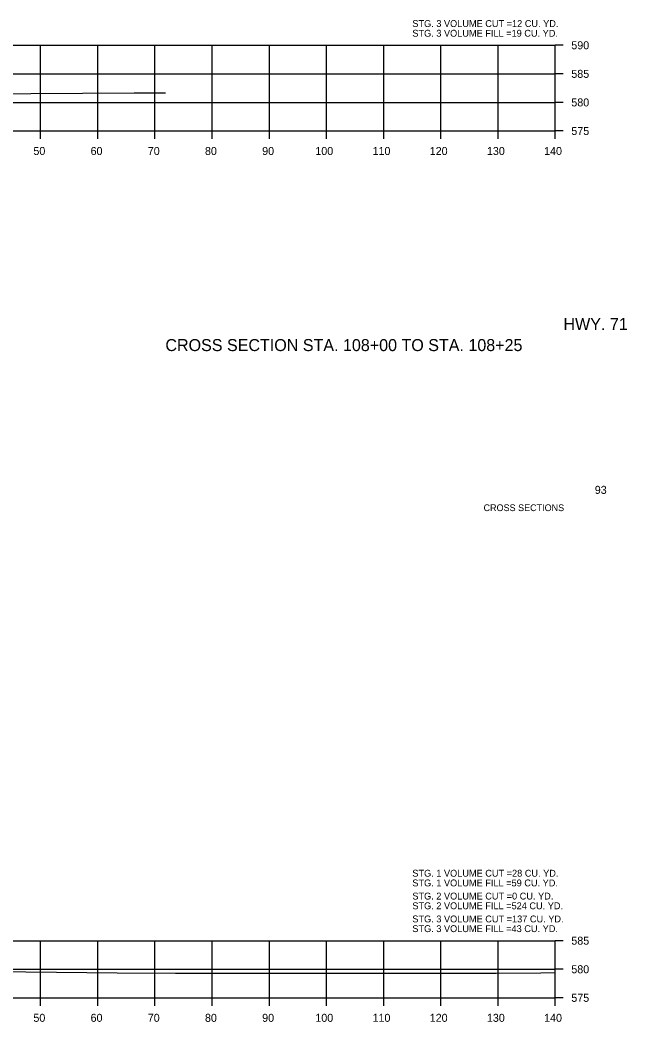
# Model space of a CAD drawing. Extents: x 642114 to 642416, y 286928 to 293347.
# Drawn here: x 642306.6 to 642412.8, y 288365.5 to 288540.8 of the extents above; entities that cross this region are included whole.
import ezdxf

# ---------------------------------------------------------------- set-up
doc = ezdxf.new("R2010")
doc.units = 0
for name, color, linetype in [('R_Axis', 7, 'Continuous'), ('R_Axis Annot', 7, 'Continuous'), ('R_Border', 7, 'Continuous'), ('R_Border Notes', 7, 'Continuous'), ('R_Draft', 7, 'Continuous'), ('R_Exist Surface Annot', 7, 'Continuous'), ('R_Grid', 7, 'Continuous')]:
    doc.layers.add(name, color=color, linetype=linetype)

msp = doc.modelspace()

# ---------------------------------------------------------------- linework, layer by layer
at = {"layer": 'R_Axis'}
for p, q in [((642400.24, 288521.41), (642400.24, 288536.41)), ((642401.64, 288536.41), (642400.24, 288536.41)), ((642401.64, 288531.41), (642400.24, 288531.41)), ((642401.64, 288526.41), (642400.24, 288526.41)), ((642120.24, 288521.41), (642400.24, 288521.41)), ((642310.24, 288520.01), (642310.24, 288521.41)), ((642320.24, 288520.01), (642320.24, 288521.41)), ((642330.24, 288520.01), (642330.24, 288521.41)), ((642340.24, 288520.01), (642340.24, 288521.41)), ((642350.24, 288520.01), (642350.24, 288521.41)), ((642360.24, 288520.01), (642360.24, 288521.41)), ((642370.24, 288520.01), (642370.24, 288521.41)), ((642380.24, 288520.01), (642380.24, 288521.41)), ((642390.24, 288520.01), (642390.24, 288521.41)), ((642400.24, 288520.01), (642400.24, 288521.41)), ((642401.64, 288521.41), (642400.24, 288521.41)), ((642400.24, 288369.74), (642400.24, 288379.74)), ((642401.64, 288379.74), (642400.24, 288379.74)), ((642401.64, 288374.74), (642400.24, 288374.74)), ((642120.24, 288369.74), (642400.24, 288369.74)), ((642310.24, 288368.34), (642310.24, 288369.74)), ((642320.24, 288368.34), (642320.24, 288369.74)), ((642330.24, 288368.34), (642330.24, 288369.74)), ((642340.24, 288368.34), (642340.24, 288369.74)), ((642350.24, 288368.34), (642350.24, 288369.74)), ((642360.24, 288368.34), (642360.24, 288369.74)), ((642370.24, 288368.34), (642370.24, 288369.74)), ((642380.24, 288368.34), (642380.24, 288369.74)), ((642390.24, 288368.34), (642390.24, 288369.74)), ((642400.24, 288368.34), (642400.24, 288369.74)), ((642401.64, 288369.74), (642400.24, 288369.74))]:
    msp.add_line(p, q, dxfattribs=at)
at = {"layer": 'R_Exist Surface Annot'}
for points in [[(642120.24, 288524.97), (642128.82, 288525.18), (642168.88, 288526.35), (642172.53, 288526.36), (642180.57, 288526.3), (642201.64, 288526.16), (642204.73, 288526.94), (642211.46, 288528.63), (642213.45, 288529.02), (642215.8, 288529.5), (642219.9, 288529.52), (642222.64, 288529.52), (642227.61, 288529.43), (642234.27, 288529.39), (642239.76, 288529.18), (642245.11, 288529.01), (642248.4, 288528.75), (642252.65, 288528.42), (642260.57, 288526.84), (642264.64, 288526.07), (642275.08, 288526.81), (642290.39, 288527.86), (642326.58, 288528.08), (642332.08, 288528.11)], [(642297.01, 288374.38), (642323.65, 288374.12), (642333.84, 288374.06), (642338.78, 288374.05), (642346.4, 288374.03), (642387.41, 288374.04), (642389.1, 288374.05), (642389.9, 288374.05), (642397.73, 288374.1), (642400.24, 288374.15)]]:
    msp.add_lwpolyline(points, dxfattribs=at)
at = {"layer": 'R_Grid'}
for p, q in [((642120.24, 288536.41), (642400.24, 288536.41)), ((642310.24, 288521.41), (642310.24, 288536.41)), ((642320.24, 288521.41), (642320.24, 288536.41)), ((642330.24, 288521.41), (642330.24, 288536.41)), ((642340.24, 288521.41), (642340.24, 288536.41)), ((642350.24, 288521.41), (642350.24, 288536.41)), ((642360.24, 288521.41), (642360.24, 288536.41)), ((642370.24, 288521.41), (642370.24, 288536.41)), ((642380.24, 288521.41), (642380.24, 288536.41)), ((642390.24, 288521.41), (642390.24, 288536.41)), ((642400.24, 288521.41), (642400.24, 288536.41)), ((642120.24, 288531.41), (642400.24, 288531.41)), ((642120.24, 288526.41), (642400.24, 288526.41)), ((642120.24, 288521.41), (642400.24, 288521.41)), ((642120.24, 288379.74), (642400.24, 288379.74)), ((642310.24, 288369.74), (642310.24, 288379.74)), ((642320.24, 288369.74), (642320.24, 288379.74)), ((642330.24, 288369.74), (642330.24, 288379.74)), ((642340.24, 288369.74), (642340.24, 288379.74)), ((642350.24, 288369.74), (642350.24, 288379.74)), ((642360.24, 288369.74), (642360.24, 288379.74)), ((642370.24, 288369.74), (642370.24, 288379.74)), ((642380.24, 288369.74), (642380.24, 288379.74)), ((642390.24, 288369.74), (642390.24, 288379.74)), ((642400.24, 288369.74), (642400.24, 288379.74)), ((642120.24, 288374.74), (642400.24, 288374.74)), ((642120.24, 288369.74), (642400.24, 288369.74))]:
    msp.add_line(p, q, dxfattribs=at)

# ---------------------------------------------------------------- texts
at = {"layer": 'R_Axis Annot'}
for s, height, p in [('590', 1.4, (642403.04, 288535.71)), ('585', 1.4, (642403.04, 288530.71)), ('580', 1.4, (642403.04, 288525.71)), ('575', 1.4, (642403.04, 288520.71)), ('50', 1.4, (642308.98, 288517.21)), ('60', 1.4, (642318.98, 288517.21)), ('70', 1.4, (642328.98, 288517.21)), ('80', 1.4, (642338.98, 288517.21)), ('90', 1.4, (642348.98, 288517.21)), ('100', 1.4, (642358.28, 288517.21)), ('110', 1.4, (642368.28, 288517.21)), ('120', 1.4, (642378.28, 288517.21)), ('130', 1.4, (642388.28, 288517.21)), ('140', 1.4, (642398.28, 288517.21)), ('HWY. 71', 2.1, (642401.67, 288486.58)), ('CROSS SECTION STA. 108+00 TO STA. 108+25', 2.1, (642332.06, 288482.9)), ('585', 1.4, (642403.04, 288379.04)), ('580', 1.4, (642403.04, 288374.04)), ('575', 1.4, (642403.04, 288369.04)), ('50', 1.4, (642308.98, 288365.54)), ('60', 1.4, (642318.98, 288365.54)), ('70', 1.4, (642328.98, 288365.54)), ('80', 1.4, (642338.98, 288365.54)), ('90', 1.4, (642348.98, 288365.54)), ('100', 1.4, (642358.28, 288365.54)), ('110', 1.4, (642368.28, 288365.54)), ('120', 1.4, (642378.28, 288365.54)), ('130', 1.4, (642388.28, 288365.54)), ('140', 1.4, (642398.28, 288365.54))]:
    msp.add_text(s, height=height, dxfattribs=at).set_placement(p)
at = {"layer": 'R_Border'}
msp.add_text('93', height=1.4, dxfattribs=at).set_placement((642407.14, 288457.92))
at = {"layer": 'R_Border Notes'}
msp.add_text('    CROSS SECTIONS    ', height=1.178, dxfattribs=at).set_placement((642385.94, 288454.9))
at = {"layer": 'R_Draft'}
for s, p in [('STG. 3 VOLUME CUT =12 CU. YD.', (642375.24, 288539.61)), ('STG. 3 VOLUME FILL =19 CU. YD.', (642375.24, 288537.91)), ('STG. 1 VOLUME CUT =28 CU. YD.', (642375.24, 288390.94)), ('STG. 1 VOLUME FILL =59 CU. YD.', (642375.24, 288389.24)), ('STG. 2 VOLUME CUT =0 CU. YD.', (642375.24, 288386.94)), ('STG. 2 VOLUME FILL =524 CU. YD.', (642375.24, 288385.24)), ('STG. 3 VOLUME CUT =137 CU. YD.', (642375.24, 288382.94)), ('STG. 3 VOLUME FILL =43 CU. YD.', (642375.24, 288381.24))]:
    msp.add_text(s, height=1.2, dxfattribs=at).set_placement(p)

doc.saveas('drawing.dxf')
